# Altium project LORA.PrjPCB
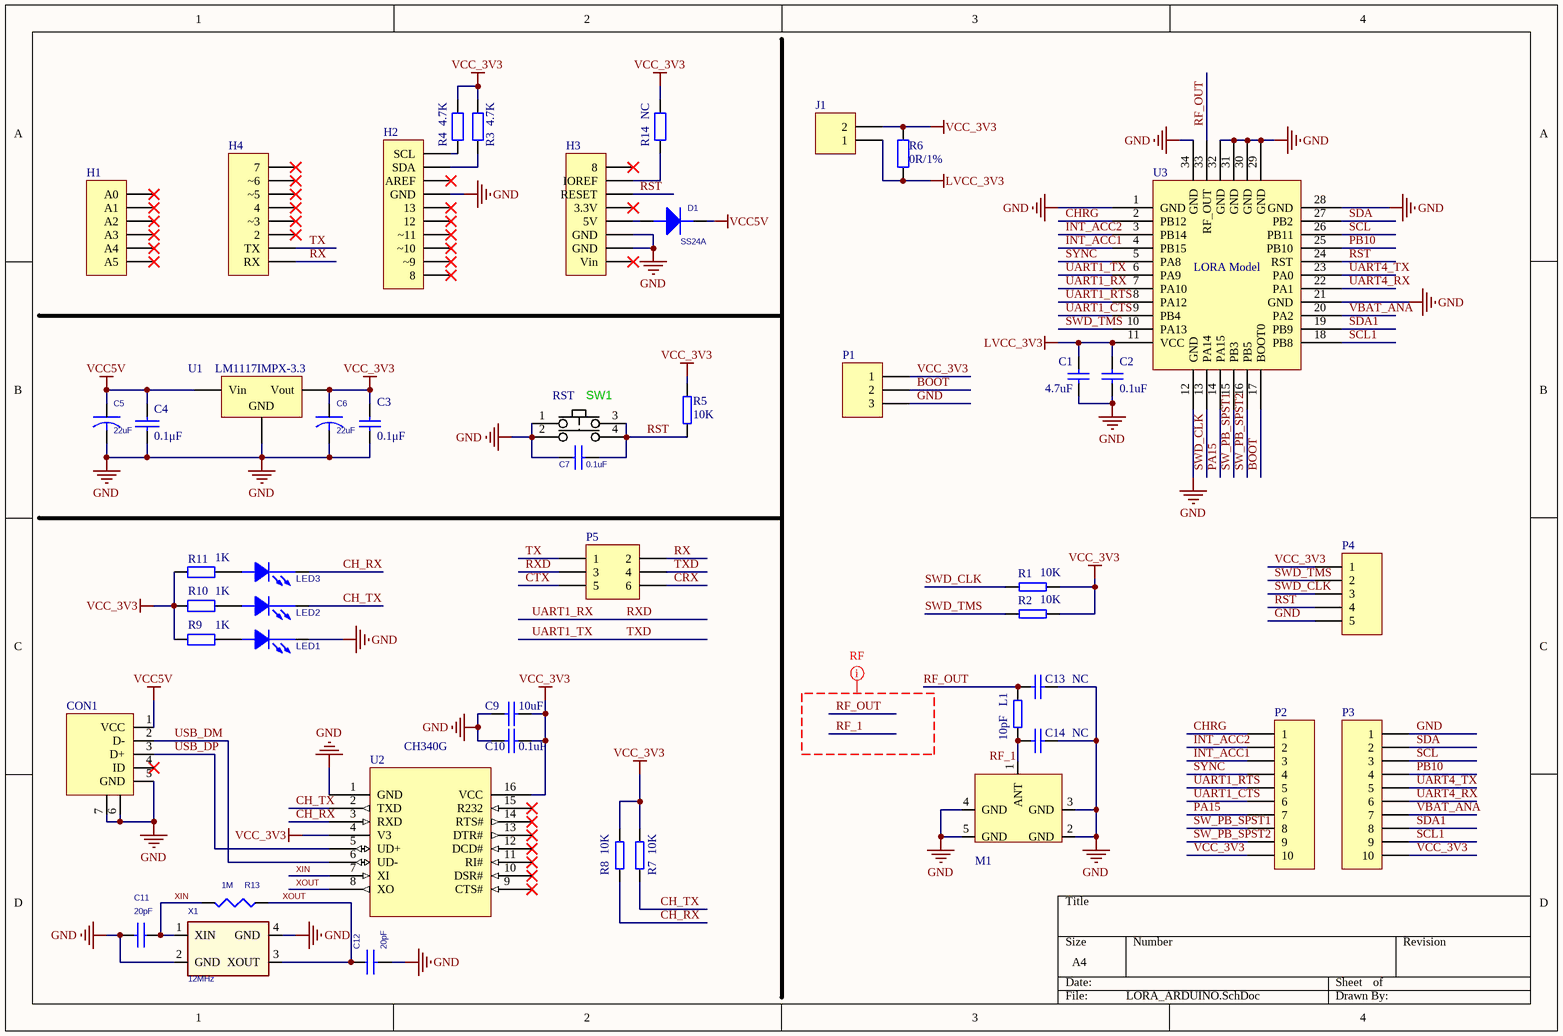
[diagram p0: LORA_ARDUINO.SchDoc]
1 sheet, 48 parts. Net scope: global (net labels, ports and power ports of the same name join across sheets).
Board file: LORA_ARDUINO.PcbDoc

## Sheet LORA_ARDUINO.SchDoc
size A4

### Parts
C1  value 4.7uF  [0603AC]  (hidden comment: Cap)
C2  value 0.1uF  [0603AC]  (hidden comment: Cap)
C3  0.1μF  [0603AC]
C4  0.1μF  [0603AC]
C5  22uF  [3216]
C6  22uF  [3216]
C7  0.1uF  [0603AC]
C9  10uF  [0603AC]
C10  0.1uF  [0603AC]
C11  20pF  [0603AC]
C12  20pF  [0603AC]
C13  NC  [0603AC]
C14  NC  [0603AC]
CON1  MICRO USB  [Micro USB通用]  (value not drawn)
D1  SS24A  [SMA/DO-214A]
H1  (no value)  [HDR1X6]
H2  (no value)  [HDR1X10]
H3  (no value)  [HDR1X8]
H4  (no value)  [HDR1X8]
J1  (no value)  [HDR1X2]
L1  10pF  [0603AR]
LED1  (no value)  [LED0603]
LED2  (no value)  [LED0603]
LED3  (no value)  [LED0603]
M1  MCX-KWE  [SMA-KWE天线底座]  (value not drawn)
P1  (no value)  [HDR1X3]
P2  (no value)  [HDR1X10]
P3  (no value)  [HDR1X10]
P4  (no value)  [HDR1X5]
P5  (no value)  [HDR2X3]
R1  10K  [0603AR]
R2  10K  [0603AR]
R3  4.7K  [0603AR]
R4  4.7K  [0603AR]
R5  10K  [0603AR]
R6  0R/1%  [1206]
R7  10K  [0603AR]
R8  10K  [0603AR]
R9  1K  [0603AR]
R10  1K  [0603AR]
R11  1K  [0603AR]
R13  1M  [0603AR]
R14  NC  [0603AR]
SW1  KEY3  [YH/4脚SMD轻触开关_3D_2]  (value not drawn)
U1  LM1117IMPX-3.3  [SOT-223]
U2  CH340G  [SOIC16 - խ]
U3  LORA Model  [LORA]
X1  12MHz  [XTAL-3.2X2.5]

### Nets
GND: C1.1 C2.1 C3.1 C4.1 C5.2 C6.2 C7.1 C9.2 C10.1 C11.2 C12.2 C13.1 C14.1 CON1.5(GND) CON1.6(GND) CON1.7(GND) H2.7(GND) H3.2(GND) H3.3(GND) LED1.2(CATHODE) M1.2(GND) M1.3(GND) M1.4(GND) M1.5(GND) P1.3 P3.1 P4.5 SW1.1 SW1.2 U1.3(GND) U2.1(GND) U3.1(GND) U3.12(GND) U3.21(GND) U3.28(GND) U3.29(GND) U3.30(GND) U3.31(GND) U3.32(GND) U3.34(GND) X1.2(GND) X1.4(GND)
LVCC_3V3: C1.2 C2.2 J1.1 R6.2 U3.11(VCC)
VCC5V: C4.2 C5.1 CON1.1(VCC) D1.2 U1.1(Vin)
VCC_3V3: C3.2 C6.1 C9.1 C10.2 J1.2 P1.1 P2.10 P3.10 P4.1 R1.1 R2.1 R3.1 R4.1 R5.2 R6.1 R7.2 R8.2 R9.2 R10.2 R11.2 R14.1 U1.2(Vout) U2.4(V3) U2.16(VCC)
BOOT: P1.2 U3.17(BOOT0)
CH_RX: LED3.2(CATHODE) R8.1 U2.3(RXD)
CH_TX: LED2.2(CATHODE) R7.1 U2.2(TXD)
CHRG: P2.1 U3.2(PB12)
CRX: P5.6
CTX: P5.5
INT_ACC1: P2.3 U3.4(PB15)
INT_ACC2: P2.2 U3.3(PB14)
PA15: P2.7 U3.14(PA15)
PB10: P3.4 U3.25(PB10)
RF_1: C14.2 L1.2 M1.1(ANT)
RF_OUT: C13.2 L1.1 U3.33(RF_OUT)
RST: C7.2 H3.6(RESET) P4.4 R5.1 SW1.3 SW1.4 U3.24(RST)
RX: H4.1(RX) P5.2
RXD: P5.3 U3.7(PA10)  [also labelled UART1_RX]
SCL: P3.3 U3.26(PB11)
SCL1: P3.9 U3.18(PB8)
SDA: P3.2 U3.27(PB2)
SDA1: P3.8 U3.19(PB9)
SW_PB_SPST1: P2.8 U3.15(PB3)
SW_PB_SPST2: P2.9 U3.16(PB5)
SWD_CLK: P4.3 R1.2 U3.13(PA14)
SWD_TMS: P4.2 R2.2 U3.10(PA13)
SYNC: P2.4 U3.5(PA8)
TX: H4.2(TX) P5.1
TXD: P5.4 U3.6(PA9)  [also labelled UART1_TX]
UART1_CTS: P2.6 U3.9(PB4)
UART1_RTS: P2.5 U3.8(PA12)
UART4_RX: P3.6 U3.22(PA1)
UART4_TX: P3.5 U3.23(PA0)
USB_DM: CON1.2(D-) U2.6(UD-)
USB_DP: CON1.3(D+) U2.5(UD+)
VBAT_ANA: P3.7 U3.20(PA2)
XIN: C11.1 R13.2 U2.7(XI) X1.1(XIN)
XOUT: C12.1 R13.1 U2.8(XO) X1.3(XOUT)
NetD1_1: D1.1 H3.4(5V)
NetH2_9: H2.9(SDA) R3.2
NetH2_10: H2.10(SCL) R4.2
NetH3_7: H3.7(IOREF) R14.2
NetLED1_1: LED1.1(ANODE) R9.1
NetLED2_1: LED2.1(ANODE) R10.1
NetLED3_1: LED3.1(ANODE) R11.1

Not connected (* = marked no-connect by the designer): CON1 4(ID)*; H1 1(A0)* 2(A1)* 3(A2)* 4(A3)* 5(A4)* 6(A5)*; H2 1(8)* 2(~9)* 3(~10)* 4(~11)* 5(12)* 6(13)* 8(AREF)*; H3 1(Vin)* 5(3.3V)* 8*; H4 3(2)* 4(~3)* 5(4)* 6(~5)* 7(~6)* 8(7)*; U2 9(CTS#)* 10(DSR#)* 11(RI#)* 12(DCD#)* 13(DTR#)* 14(RTS#)* 15(R232)*

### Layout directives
net class RF: RF_1, RF_OUT

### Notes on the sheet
- (near SW1) RST

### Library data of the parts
C1-C3 = Cap: Capacitor
C4 C9 C10 C13 C14 = CAP: Capacitor
C5 C6 = CAP: CISPartType: Capacitor\1206; ATHEROS KEY: 034-226CK-004; AtherosDescription: CAP,1206,X5R,22uF,+/-10%,25V; Voltage: 25V; Tolerance: +/-10%
C7 = C
C11 C12 = CAP NP_Dup1
D1 = DIODE
H1 = Header 6: Header, 6-Pin
H2 P2 P3 = Header 10: Header, 10-Pin
H3 H4 = Header 8: Header, 8-Pin
J1 = Header 2: Header, 2-Pin
L1 R1 R2 R5 R7 R8 = RES
LED1-LED3 = LED
P1 = Header 3: Header, 3-Pin
P4 = Header 5: Header, 5-Pin
P5 = Header 3X2: Header, 3-Pin, Dual row
R3 R4 R9-R11 R14 = Res2: Resistor; Value: 10K
R6 = Res2: Resistor; Value: R2
R13 = R_0: SDTSourceLibName: C:\WINDOWS\TEMP\DEVICE.LIB
SW1 = KEY1
U1 = LM1117IMPX-3.3: Voltage Regulator
U2 = CH340G: USB to TTL Serial / UART
X1 = Crystal_SMD_2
